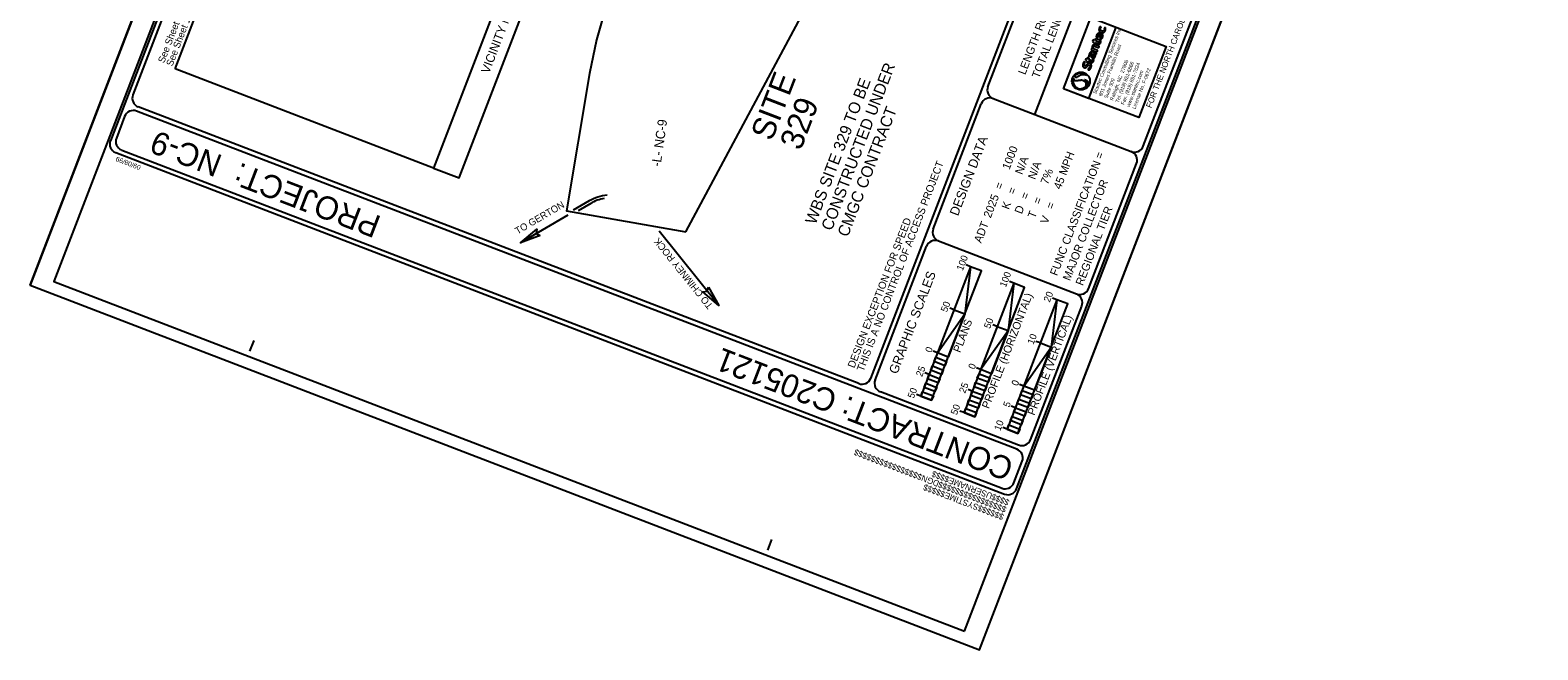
# Model space of a CAD drawing. Extents: x 1015221 to 1064345, y 619216 to 647967.
# Drawn here: x 1015221 to 1028267, y 632235 to 637598 of the extents above; entities that cross this region are included whole.
import ezdxf

# ---------------------------------------------------------------- set-up
doc = ezdxf.new("R2010")
doc.units = 0
for name, color, linetype in [('Old_Level_32', 7, 'Continuous'), ('Old_Level_8', 7, 'Continuous'), ('Prop Dimension', 7, 'Continuous'), ('Prop DSN Text', 7, 'Continuous'), ('Prop Shade Light', 7, 'Continuous'), ('Prop Terminator CELL', 7, 'Continuous'), ('Scratch_Level_0', 7, 'Continuous'), ('Scratch_Level_2', 7, 'Continuous'), ('Sheet Cutting Line CELL', 7, 'Continuous'), ('Sheet Data Field CELL', 7, 'Continuous'), ('Sheet Data Text CELL', 7, 'Continuous'), ('Sheet Plot Border Inside CELL', 7, 'Continuous'), ('Sheet Plot Border Outside CELL', 7, 'Continuous'), ('Sheet Title CELL', 7, 'Continuous')]:
    doc.layers.add(name, color=color, linetype=linetype)

msp = doc.modelspace()

# ---------------------------------------------------------------- linework, layer by layer
at = {"layer": 'Prop DSN Text'}
for p, q in [((1019873, 635998), (1019464, 635758)), ((1021179, 635214), (1020662, 635859))]:
    msp.add_line(p, q, dxfattribs=at)
at = {"layer": 'Prop Shade Light'}
for p, q in [((1020059, 636121), (1019920, 636041)), ((1020071, 636099), (1019962, 636035))]:
    msp.add_line(p, q, dxfattribs=at)
for centre, radius, start, end in [((1020251, 635786), 386, 95.5193, 119.8722), ((1020252, 635790), 358, 100.157, 120.3223)]:
    msp.add_arc(centre, radius, start, end, dxfattribs=at)
at = {"layer": 'Prop Terminator CELL'}
for points in [[(1019635, 635822), (1019464, 635758), (1019604, 635877), (1019600, 635838)], [(1021091, 635374), (1021179, 635214), (1021041, 635335), (1021080, 635338)]]:
    msp.add_lwpolyline(points, close=True, dxfattribs=at)
at = {"layer": 'Scratch_Level_0'}
msp.add_lwpolyline([(1024163, 637091), (1024399, 637707), (1024616, 637624), (1024379, 637008)], close=True, dxfattribs=at)
at = {"layer": 'Scratch_Level_2'}
msp.add_lwpolyline([(1020895, 635854), (1022474, 638806), (1023379, 639474), (1023843, 640900), (1023637, 641036), (1023148, 642069), (1023188, 643043), (1024411, 644926), (1023531, 645498), (1022161, 643389), (1022151, 643383), (1022046, 641943), (1021939, 640557), (1021513, 639679), (1020439, 638632), (1020121, 637513), (1020060, 637224), (1019861, 636036)], close=True, dxfattribs=at)
at = {"layer": 'Sheet Cutting Line CELL'}
for p, q in [((1015221, 635391), (1020052, 647967)), ((1023435, 632235), (1028267, 644811)), ((1015221, 635391), (1023435, 632235))]:
    msp.add_line(p, q, dxfattribs=at)
at = {"layer": 'Sheet Data Field CELL'}
for p, q in [((1023358, 635551), (1023321, 635566)), ((1023215, 635178), (1023178, 635192)), ((1023000, 634618), (1022962, 634632)), ((1022928, 634431), (1022891, 634446)), ((1023727, 633554), (1023727, 633554))]:
    msp.add_line(p, q, dxfattribs=at)
at = {"layer": 'Sheet Data Text CELL'}
for p, q in [((1024475, 637532), (1024489, 637568)), ((1024406, 637441), (1024401, 637429)), ((1024412, 637440), (1024406, 637441)), ((1024416, 637515), (1024414, 637499)), ((1024414, 637499), (1024426, 637494)), ((1024431, 637509), (1024416, 637515)), ((1024452, 637426), (1024422, 637437)), ((1024426, 637494), (1024423, 637485)), ((1024423, 637485), (1024432, 637482)), ((1024439, 637527), (1024431, 637509)), ((1024432, 637482), (1024436, 637491)), ((1024447, 637520), (1024439, 637527)), ((1024441, 637505), (1024447, 637520)), ((1024466, 637495), (1024441, 637505)), ((1024474, 637557), (1024466, 637535)), ((1024351, 637318), (1024342, 637326)), ((1024354, 637354), (1024352, 637338)), ((1024352, 637338), (1024364, 637334)), ((1024370, 637348), (1024354, 637354)), ((1024364, 637334), (1024361, 637325)), ((1024361, 637325), (1024371, 637321)), ((1024377, 637366), (1024370, 637348)), ((1024371, 637321), (1024374, 637330)), ((1024385, 637359), (1024377, 637366)), ((1024380, 637344), (1024385, 637359)), ((1024405, 637334), (1024380, 637344)), ((1024383, 637371), (1024393, 637372)), ((1024401, 637429), (1024446, 637412)), ((1024418, 637393), (1024429, 637389))]:
    msp.add_line(p, q, dxfattribs=at)
msp.add_lwpolyline([(1024163, 637091), (1024399, 637707), (1025050, 637457), (1024814, 636841)], close=True, dxfattribs=at)
for points in [[(1024249, 637184), (1024249, 637184)], [(1024276, 637216), (1024276, 637216)]]:
    msp.add_lwpolyline(points, dxfattribs=at)
msp.add_circle((1024313, 637158), 77.5, dxfattribs=at)
for start, end in [(157.7496, 272.6675), (157.7432, 157.7496), (42.7645, 122.4156), (316.1014, 320.441)]:
    msp.add_arc((1024313, 637158), 68.3, start, end, dxfattribs=at)
for points, degree in [([(1024489, 637568), (1024487, 637568), (1024484, 637570), (1024478, 637571), (1024471, 637572), (1024465, 637571), (1024460, 637569), (1024455, 637566), (1024451, 637562), (1024448, 637556), (1024446, 637550), (1024446, 637543), (1024446, 637537), (1024449, 637532), (1024453, 637527), (1024457, 637523), (1024463, 637520), (1024469, 637518), (1024475, 637517), (1024481, 637517), (1024487, 637519), (1024492, 637522), (1024498, 637528), (1024501, 637535), (1024503, 637541), (1024504, 637547), (1024504, 637553), (1024502, 637557), (1024500, 637559), (1024497, 637560), (1024495, 637559), (1024493, 637558), (1024492, 637556), (1024492, 637553), (1024493, 637550), (1024493, 637546), (1024493, 637542), (1024492, 637539), (1024489, 637536), (1024486, 637534), (1024483, 637532), (1024479, 637531), (1024477, 637531), (1024475, 637532), (1024475, 637532)], 3), ([(1024482, 637632), (1024481, 637631), (1024478, 637628), (1024475, 637623), (1024471, 637616), (1024469, 637608), (1024469, 637600), (1024470, 637593), (1024474, 637586), (1024479, 637581), (1024486, 637577), (1024494, 637575), (1024501, 637575), (1024507, 637577), (1024513, 637580), (1024519, 637586), (1024524, 637593), (1024526, 637601), (1024527, 637608), (1024526, 637614), (1024525, 637618), (1024522, 637619), (1024519, 637620), (1024518, 637619), (1024516, 637618), (1024515, 637616), (1024515, 637614), (1024516, 637611), (1024516, 637608), (1024516, 637604), (1024515, 637600), (1024513, 637596), (1024509, 637593), (1024505, 637591), (1024500, 637590), (1024495, 637591), (1024491, 637592), (1024487, 637594), (1024483, 637598), (1024481, 637601), (1024480, 637606), (1024480, 637610), (1024482, 637615), (1024484, 637619), (1024487, 637623), (1024489, 637624), (1024490, 637625)], 3), ([(1024422, 637437), (1024422, 637438), (1024421, 637439), (1024421, 637442), (1024420, 637446), (1024420, 637450), (1024422, 637454), (1024424, 637457), (1024428, 637459), (1024432, 637459), (1024436, 637458), (1024443, 637455), (1024451, 637452), (1024458, 637449), (1024462, 637448), (1024466, 637448), (1024469, 637450), (1024470, 637454), (1024470, 637457), (1024469, 637460), (1024466, 637463), (1024459, 637465), (1024451, 637468), (1024442, 637471), (1024436, 637474), (1024431, 637475), (1024427, 637475), (1024423, 637474), (1024418, 637471), (1024414, 637467), (1024412, 637461), (1024410, 637456), (1024410, 637451), (1024410, 637446), (1024411, 637442), (1024412, 637440), (1024412, 637440)], 3), ([(1024436, 637491), (1024445, 637487), (1024454, 637484), (1024465, 637480), (1024467, 637479), (1024471, 637479), (1024474, 637480), (1024477, 637481), (1024479, 637483), (1024481, 637486), (1024483, 637490), (1024485, 637495), (1024486, 637500), (1024486, 637504), (1024485, 637507), (1024483, 637510), (1024481, 637511), (1024479, 637511), (1024477, 637510), (1024476, 637509), (1024475, 637508), (1024475, 637507), (1024475, 637505), (1024475, 637504), (1024476, 637502), (1024476, 637500), (1024476, 637498), (1024475, 637496), (1024473, 637494), (1024471, 637494), (1024469, 637494), (1024467, 637495), (1024466, 637495)], 3), ([(1024466, 637535), (1024466, 637535), (1024464, 637536), (1024462, 637537), (1024460, 637538), (1024458, 637541), (1024456, 637545), (1024456, 637549), (1024458, 637553), (1024460, 637556), (1024463, 637558), (1024467, 637558), (1024471, 637558), (1024473, 637557), (1024474, 637557)], 3), ([(1024342, 637326), (1024342, 637325), (1024339, 637323), (1024336, 637318), (1024333, 637312), (1024330, 637306), (1024329, 637301), (1024328, 637296), (1024328, 637290), (1024329, 637285), (1024332, 637280), (1024335, 637277), (1024339, 637275), (1024343, 637273), (1024346, 637273), (1024350, 637273), (1024353, 637274), (1024356, 637275), (1024359, 637277), (1024362, 637280), (1024366, 637283), (1024369, 637286), (1024373, 637290), (1024376, 637293), (1024380, 637295), (1024383, 637296), (1024386, 637296), (1024388, 637295), (1024390, 637292), (1024392, 637289), (1024392, 637285), (1024391, 637280), (1024389, 637276), (1024386, 637272), (1024383, 637269), (1024381, 637267), (1024379, 637265), (1024377, 637264), (1024376, 637263), (1024375, 637261), (1024375, 637259), (1024376, 637257), (1024377, 637255), (1024379, 637254), (1024382, 637254), (1024384, 637255), (1024388, 637256), (1024393, 637261), (1024397, 637267), (1024400, 637273), (1024402, 637279), (1024404, 637284), (1024404, 637289), (1024404, 637295), (1024402, 637301), (1024399, 637306), (1024394, 637309), (1024390, 637311), (1024386, 637312), (1024382, 637312), (1024377, 637311), (1024373, 637309), (1024369, 637306), (1024365, 637302), (1024361, 637298), (1024357, 637294), (1024354, 637291), (1024350, 637289), (1024347, 637289), (1024345, 637290), (1024342, 637291), (1024341, 637294), (1024340, 637297), (1024340, 637300), (1024342, 637304), (1024343, 637307), (1024345, 637310), (1024347, 637313), (1024349, 637316), (1024350, 637318), (1024351, 637318)], 3), ([(1024374, 637330), (1024383, 637326), (1024392, 637323), (1024403, 637319), (1024405, 637318), (1024409, 637318), (1024412, 637319), (1024415, 637320), (1024417, 637322), (1024419, 637325), (1024422, 637329), (1024423, 637334), (1024424, 637339), (1024424, 637343), (1024423, 637347), (1024421, 637349), (1024419, 637350), (1024417, 637350), (1024415, 637349), (1024414, 637349), (1024414, 637347), (1024413, 637346), (1024413, 637344), (1024413, 637343), (1024414, 637341), (1024414, 637339), (1024414, 637337), (1024413, 637335), (1024411, 637334), (1024410, 637333), (1024407, 637333), (1024406, 637334), (1024405, 637334)], 3), ([(1024437, 637387), (1024437, 637387), (1024438, 637387), (1024441, 637387), (1024443, 637388), (1024446, 637391), (1024447, 637394), (1024447, 637397), (1024445, 637399), (1024443, 637400), (1024440, 637401), (1024431, 637403), (1024422, 637407), (1024412, 637411), (1024406, 637412), (1024401, 637411), (1024397, 637409), (1024392, 637405), (1024389, 637400), (1024385, 637393), (1024383, 637386), (1024382, 637378), (1024383, 637373), (1024383, 637371)], 3), ([(1024393, 637372), (1024393, 637373), (1024392, 637375), (1024393, 637379), (1024393, 637383), (1024394, 637387), (1024396, 637390), (1024398, 637393), (1024401, 637396), (1024404, 637397), (1024407, 637397), (1024409, 637396), (1024410, 637396)], 3), ([(1024410, 637396), (1024409, 637395), (1024408, 637392), (1024406, 637387), (1024404, 637381), (1024403, 637374), (1024404, 637368), (1024406, 637362), (1024411, 637358), (1024416, 637356), (1024421, 637355), (1024426, 637356), (1024431, 637359), (1024435, 637364), (1024437, 637370), (1024439, 637376), (1024439, 637380), (1024438, 637384), (1024437, 637386), (1024437, 637387)], 3), ([(1024429, 637389), (1024429, 637388), (1024430, 637386), (1024430, 637384), (1024430, 637380), (1024429, 637376), (1024427, 637373), (1024425, 637371), (1024423, 637371), (1024420, 637371), (1024418, 637371), (1024416, 637372), (1024415, 637375), (1024414, 637377), (1024414, 637380), (1024415, 637384), (1024416, 637387), (1024417, 637391), (1024418, 637392), (1024418, 637393)], 3), ([(1024446, 637412), (1024447, 637412), (1024449, 637412), (1024451, 637412), (1024454, 637414), (1024456, 637417), (1024457, 637421), (1024455, 637424), (1024453, 637425), (1024452, 637426), (1024452, 637426)], 3), ([(1024249, 637184), (1024249, 637182), (1024249, 637178), (1024252, 637172), (1024258, 637165), (1024267, 637162), (1024277, 637162), (1024287, 637164), (1024298, 637165), (1024309, 637167), (1024319, 637167), (1024330, 637166), (1024339, 637161), (1024347, 637155), (1024353, 637146), (1024356, 637137), (1024356, 637128), (1024356, 637120), (1024353, 637113), (1024348, 637105), (1024341, 637098), (1024331, 637092), (1024322, 637091), (1024316, 637090)], 3), ([(1024249, 637184), (1024249, 637184), (1024249, 637184), (1024249, 637184)], 2), ([(1024363, 637204), (1024361, 637206), (1024357, 637208), (1024350, 637211), (1024344, 637212), (1024338, 637213), (1024331, 637213), (1024322, 637212), (1024314, 637210), (1024305, 637206), (1024295, 637199), (1024285, 637194), (1024277, 637189), (1024270, 637189), (1024265, 637190), (1024263, 637194), (1024262, 637198), (1024263, 637202), (1024266, 637206), (1024270, 637211), (1024274, 637214), (1024276, 637216)], 3), ([(1024344, 637169), (1024346, 637169), (1024350, 637169), (1024357, 637166), (1024364, 637162), (1024370, 637156), (1024374, 637148), (1024374, 637139), (1024373, 637131), (1024370, 637122), (1024367, 637117), (1024365, 637115)], 3), ([(1024362, 637111), (1024363, 637112), (1024364, 637116), (1024366, 637123), (1024367, 637130), (1024365, 637138), (1024364, 637145), (1024360, 637153), (1024355, 637160), (1024349, 637166), (1024346, 637168), (1024344, 637169)], 3)]:
    msp.add_open_spline(points, degree=degree, dxfattribs=at)
at = {"layer": 'Sheet Plot Border Inside CELL'}
msp.add_lwpolyline([(1023305, 632397), (1028086, 644842), (1020207, 647869), (1015425, 635424)], close=True, dxfattribs=at)
at = {"layer": 'Sheet Plot Border Outside CELL'}
msp.add_lwpolyline([(1020052, 647967), (1015221, 635391), (1023435, 632235), (1028267, 644811)], close=True, dxfattribs=at)
at = {"layer": 'Sheet Title CELL'}
for p, q in [((1022495, 634585), (1026569, 645189)), ((1023508, 637109), (1024598, 639947)), ((1023914, 636868), (1025062, 639855)), ((1022392, 634539), (1016156, 636934)), ((1023035, 635877), (1023451, 636960)), ((1023554, 637006), (1024749, 636547)), ((1023759, 633971), (1016142, 636897)), ((1023081, 635774), (1024275, 635315)), ((1022533, 634570), (1022977, 635728)), ((1023358, 635551), (1022928, 634431)), ((1023021, 634395), (1023452, 635515)), ((1023358, 635551), (1023321, 635566)), ((1023452, 635515), (1023358, 635551)), ((1023732, 635408), (1023302, 634288)), ((1023732, 635408), (1023302, 634288)), ((1023395, 634252), (1023825, 635372)), ((1023732, 635408), (1023694, 635422)), ((1023732, 635408), (1023694, 635422)), ((1023825, 635372), (1023732, 635408)), ((1024105, 635264), (1023675, 634144)), ((1024105, 635264), (1023675, 634144)), ((1024105, 635264), (1023675, 634144)), ((1023768, 634108), (1024199, 635229)), ((1024105, 635264), (1024068, 635279)), ((1024105, 635264), (1024068, 635279)), ((1024105, 635264), (1024068, 635279)), ((1024199, 635229), (1024105, 635264)), ((1023215, 635178), (1023178, 635192)), ((1023215, 635178), (1023308, 635142)), ((1023588, 635035), (1023551, 635049)), ((1023588, 635035), (1023551, 635049)), ((1023588, 635035), (1023682, 634999)), ((1017122, 634819), (1017158, 634913)), ((1017122, 634819), (1017158, 634913)), ((1023962, 634891), (1023924, 634905)), ((1023962, 634891), (1023924, 634905)), ((1023962, 634891), (1023924, 634905)), ((1023962, 634891), (1024055, 634855)), ((1023072, 634805), (1023034, 634819)), ((1023000, 634618), (1022962, 634632)), ((1023028, 634693), (1023122, 634657)), ((1023445, 634661), (1023408, 634675)), ((1023445, 634661), (1023408, 634675)), ((1023773, 634008), (1022578, 634467)), ((1022928, 634431), (1022891, 634446)), ((1022891, 634446), (1022891, 634446)), ((1023373, 634475), (1023336, 634489)), ((1023373, 634475), (1023336, 634489)), ((1023402, 634549), (1023495, 634513)), ((1023818, 634518), (1023781, 634532)), ((1023818, 634518), (1023781, 634532)), ((1023818, 634518), (1023781, 634532)), ((1022928, 634431), (1023021, 634395)), ((1022928, 634431), (1022928, 634431)), ((1023747, 634331), (1023709, 634345)), ((1023747, 634331), (1023709, 634345)), ((1023747, 634331), (1023709, 634345)), ((1023775, 634406), (1023869, 634370)), ((1023302, 634288), (1023264, 634302)), ((1023302, 634288), (1023264, 634302)), ((1023264, 634302), (1023264, 634302)), ((1023302, 634288), (1023395, 634252)), ((1023302, 634288), (1023302, 634288)), ((1023302, 634288), (1023302, 634288)), ((1023675, 634144), (1023637, 634159)), ((1023675, 634144), (1023637, 634159)), ((1023675, 634144), (1023637, 634159)), ((1023637, 634159), (1023637, 634159)), ((1023675, 634144), (1023768, 634108)), ((1023675, 634144), (1023675, 634144)), ((1023675, 634144), (1023675, 634144)), ((1023675, 634144), (1023675, 634144)), ((1023727, 633554), (1023727, 633554)), ((1023727, 633554), (1023727, 633554)), ((1023727, 633554), (1023727, 633554)), ((1023727, 633554), (1023727, 633554)), ((1021603, 633098), (1021638, 633191)), ((1021603, 633098), (1021638, 633191))]:
    msp.add_line(p, q, dxfattribs=at)
for points in [[(1020161, 647694), (1015915, 636641)], [(1020184, 647642), (1016110, 637038)], [(1023756, 633629), (1028003, 644681)], [(1024852, 636593), (1025943, 639431)], [(1016038, 636851), (1015967, 636664)], [(1015961, 636538), (1023653, 633583)], [(1015961, 636538), (1023653, 633583)], [(1016013, 636561), (1023630, 633635)], [(1024379, 635361), (1024795, 636444)], [(1023877, 634054), (1024321, 635211)], [(1023733, 633680), (1023805, 633867)]]:
    msp.add_lwpolyline(points, dxfattribs=at)
for points in [[(1016474, 637264), (1017426, 639742), (1019662, 638883), (1018710, 636405)], [(1019662, 638883), (1018710, 636405), (1018934, 636319), (1019886, 638797)], [(1023358, 635551), (1023308, 635142), (1023452, 635515)], [(1023732, 635408), (1023682, 634999), (1023825, 635372)], [(1024105, 635264), (1024055, 634855), (1024199, 635229)], [(1023072, 634805), (1023308, 635142), (1023165, 634769)], [(1023445, 634661), (1023682, 634999), (1023538, 634625)], [(1023818, 634518), (1024055, 634855), (1023912, 634482)], [(1023043, 634730), (1023057, 634767), (1023151, 634731), (1023136, 634694)], [(1022986, 634581), (1023000, 634618), (1023093, 634582), (1023079, 634545)], [(1023014, 634655), (1023028, 634693), (1023122, 634657), (1023107, 634619)], [(1023416, 634586), (1023431, 634624), (1023524, 634588), (1023510, 634551)], [(1022928, 634431), (1022942, 634469), (1023036, 634433), (1023021, 634395)], [(1022957, 634506), (1022971, 634543), (1023065, 634507), (1023050, 634470)], [(1023359, 634437), (1023373, 634475), (1023466, 634439), (1023452, 634401)], [(1023388, 634512), (1023402, 634549), (1023495, 634513), (1023481, 634476)], [(1023790, 634443), (1023804, 634480), (1023897, 634444), (1023883, 634407)], [(1023302, 634288), (1023316, 634325), (1023409, 634289), (1023395, 634252)], [(1023330, 634362), (1023344, 634400), (1023438, 634364), (1023423, 634327)], [(1023732, 634294), (1023747, 634331), (1023840, 634295), (1023826, 634258)], [(1023761, 634368), (1023775, 634406), (1023869, 634370), (1023854, 634332)], [(1023675, 634144), (1023689, 634182), (1023783, 634146), (1023768, 634108)], [(1023704, 634219), (1023718, 634256), (1023811, 634220), (1023797, 634183)]]:
    msp.add_lwpolyline(points, close=True, dxfattribs=at)
for centre, start, end in [((1023582, 637081), 158.983, 248.983), ((1016184, 637009), 158.983, 248.983), ((1023525, 636932), 68.983, 158.983), ((1016113, 636823), 68.983, 158.983), ((1016041, 636636), 158.983, 248.983), ((1015989, 636613), 158.983, 248.983), ((1024777, 636622), 248.983, 338.983), ((1024720, 636472), 338.983, 68.983), ((1023109, 635849), 158.983, 248.983), ((1023051, 635699), 68.983, 158.983), ((1024304, 635390), 248.983, 338.983), ((1024246, 635240), 338.983, 68.983), ((1022420, 634614), 248.983, 338.983), ((1022607, 634542), 158.983, 248.983), ((1023802, 634083), 248.983, 338.983), ((1023730, 633896), 338.983, 68.983), ((1023658, 633709), 248.983, 338.983), ((1023681, 633658), 248.983, 338.983)]:
    msp.add_arc(centre, 80, start, end, dxfattribs=at)

# ---------------------------------------------------------------- texts
at = {"layer": 'Old_Level_32'}
msp.add_text('VICINITY MAP', height=76.44, rotation=68.983, dxfattribs=at).set_placement((1019191, 637217))
at = {"layer": 'Old_Level_8'}
msp.add_text('FOR THE NORTH CAROLINA DEPARTMENT OF TRANSPORTATION', height=51.59, rotation=68.983, dxfattribs=at).set_placement((1024922, 636920))
at = {"layer": 'Prop Dimension'}
for s, p in [('THIS IS A NO CONTROL OF ACCESS PROJECT', (1022431, 634639)), ('DESIGN EXCEPTION FOR SPEED', (1022352, 634669))]:
    msp.add_text(s, height=64.8, rotation=68.983, dxfattribs=at).set_placement(p)
at = {"layer": 'Prop DSN Text'}
for s, height, rotation, p in [('CONSTRUCTED UNDER ', 100, 68.983, (1022156, 635856)), ('WBS SITE 329 TO BE ', 100, 68.983, (1022016, 635910)), ('CMGC CONTRACT', 100, 68.983, (1022296, 635802)), ('-L- NC-9', 80, 81.826, (1020675, 636414)), ('TO GERTON', 60, 30.3223, (1019438, 635829)), ('TO CHIMNEY ROCK', 60, 128.7017, (1021133, 635215))]:
    msp.add_text(s, height=height, rotation=rotation, dxfattribs=at).set_placement(p)
at = {"layer": 'Prop Shade Light'}
for s, p in [('SITE', (1021638, 636630)), ('329', (1021888, 636549))]:
    msp.add_text(s, height=200, rotation=68.983, dxfattribs=at).set_placement(p)
at = {"layer": 'Sheet Data Field CELL'}
for s, p in [('LENGTH ROADWAY PROJECT NC-9 ', (1023831, 637207)), ('TOTAL LENGTH PROJECT NC-9', (1023951, 637176)), ('1000', (1023694, 636385)), ('FUNC CLASSIFICATION =', (1024107, 635467)), ('45 MPH', (1024138, 636215)), ('N/A', (1023805, 636343)), ('N/A', (1023916, 636300)), ('7%', (1024026, 636257)), ('=', (1023628, 636214)), ('MAJOR COLLECTOR', (1024218, 635424)), ('2025', (1023532, 635967)), ('=', (1023739, 636171)), ('=', (1023851, 636128)), ('=', (1023960, 636086)), ('K', (1023689, 636041)), ('D', (1023801, 636002)), ('T', (1023915, 635964)), ('=', (1024072, 636043)), ('REGIONAL TIER', (1024329, 635382)), ('ADT', (1023450, 635751)), ('V', (1024024, 635916))]:
    msp.add_text(s, height=70, rotation=68.983, dxfattribs=at).set_placement(p)
at = {"layer": 'Sheet Data Text CELL'}
for s, height, p in [('Stantec Consulting Services Inc.', 30.99, (1024446, 637042)), ('801 Jones Franklin Road', 30.99, (1024494, 637023)), ('Raleigh, NC  27606', 30.99, (1024591, 636986)), ('Tel. (919) 851-6866', 30.99, (1024639, 636968)), ('Fax. (919) 851-7024', 30.99, (1024687, 636949)), ('Suite 300', 31, (1024542, 637005)), ('www.stantec.com', 30.99, (1024735, 636931)), ('License No. F-0672', 30.99, (1024784, 636912))]:
    msp.add_text(s, height=height, rotation=68.983, dxfattribs=at).set_placement(p)
at = {"layer": 'Sheet Title CELL'}
for s, height, rotation, p in [('See Sheet 1B For Convetional Symbols', 60, 68.983, (1016451, 637281)), ('See Sheet 1A For Index of Sheets', 60, 68.983, (1016380, 637309)), ('PROJECT:  NC-9', 200, 158.983, (1018269, 635982)), ('DESIGN DATA', 80, 68.983, (1023249, 635985)), ('09/08/99', 42, 158.983, (1016182, 636425)), ('100', 60, 68.983, (1023290, 635511)), ('GRAPHIC SCALES', 80, 68.983, (1022723, 634616)), ('100', 60, 68.983, (1023663, 635368)), ('50', 60, 68.983, (1023153, 635153)), ('PROFILE (HORIZONTAL)', 68, 68.983, (1023516, 634317)), ('20', 60, 68.983, (1024043, 635239)), ('PLANS', 68, 68.983, (1023268, 634802)), ('50', 60, 68.983, (1023526, 635010)), ('PROFILE (VERTICAL)', 68, 68.983, (1023911, 634259)), ('10', 60, 68.983, (1023902, 634873)), ('CONTRACT: C205121', 200, 158.983, (1023745, 633878)), ('0', 60, 68.983, (1023018, 634802)), ('0', 60, 68.983, (1023391, 634658)), ('0', 60, 68.983, (1023392, 634658)), ('25', 60, 68.983, (1022938, 634594)), ('0', 60, 68.983, (1023764, 634515)), ('0', 60, 68.983, (1023766, 634514)), ('0', 60, 68.983, (1023766, 634514)), ('50', 60, 68.983, (1022866, 634406)), ('25', 60, 68.983, (1023311, 634451)), ('50', 60, 68.983, (1023239, 634263)), ('5', 60, 68.983, (1023693, 634329)), ('10', 60, 68.983, (1023615, 634126)), ('$$$$$$$$$$$$$$$$DGN$$$$$$$$$$$$$$$$', 52.5, 158.983, (1023674, 633470)), ('$$$$USERNAME$$$$', 52.5, 158.983, (1023698, 633531)), ('$$$$$$SYSTIME$$$$$', 52.5, 158.983, (1023651, 633406))]:
    msp.add_text(s, height=height, rotation=rotation, dxfattribs=at).set_placement(p)

doc.saveas('drawing.dxf')
